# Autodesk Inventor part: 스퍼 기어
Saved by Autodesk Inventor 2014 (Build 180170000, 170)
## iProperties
Created: 2024-08
Part Number: 스퍼 기어
Material: 일반
Document SubType Name: Modeling
Designer: dg
Density: 1 g/cm^3
Appearance: 기본값
Author: dg
Author: jhkim
Creation Date: 2024-08-09
Sending System: Autodesk Inventor 2025
Preprocessor: ST-DEVELOPER v20
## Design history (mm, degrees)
node "스퍼 기어1"
node "솔리드1"
node "기준1"
